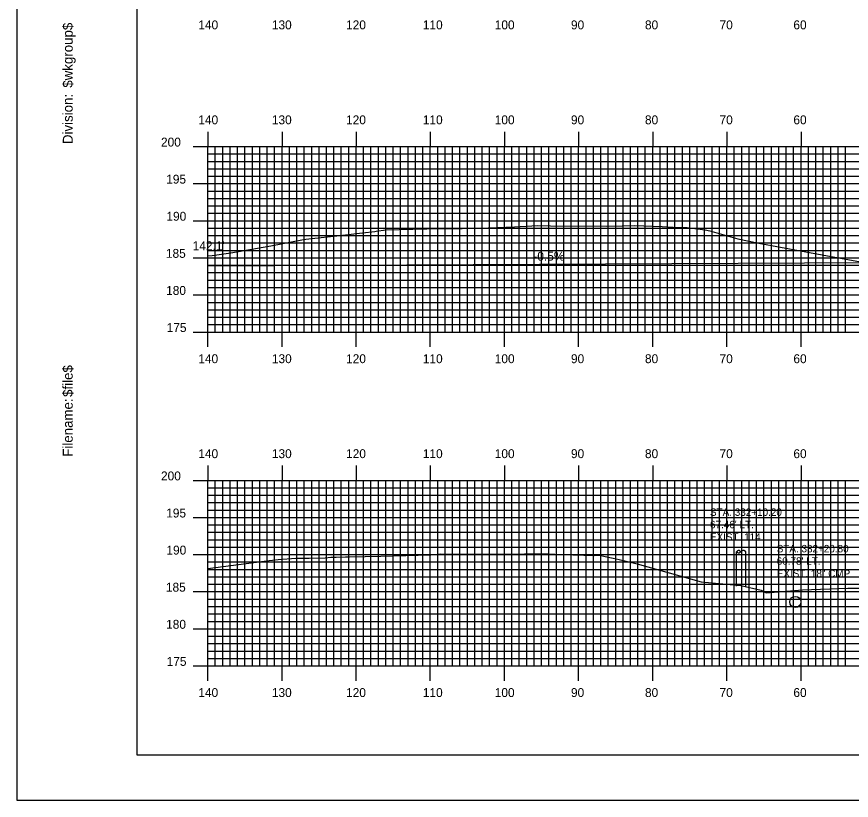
# Model space of a CAD drawing. Extents: x 1822785 to 1823129, y 442591 to 442811.
# Drawn here: x 1822785.5 to 1822898.1, y 442590.5 to 442696.2 of the extents above; entities that cross this region are included whole.
import ezdxf

# ---------------------------------------------------------------- set-up
doc = ezdxf.new("R2010")
doc.units = 0
for name, color, linetype in [('ANNOTATION', 7, 'Continuous'), ('BORDER', 7, 'Continuous'), ('D_Drainage_Culvert', 7, 'Continuous'), ('D_Text_Monospaced', 7, 'Continuous'), ('D_Text_Standard', 7, 'Continuous'), ('H_V ANNOTATION', 7, 'Continuous'), ('MAJOR', 7, 'Continuous'), ('MINOR', 7, 'Continuous'), ('PLOT BOUNDARY', 7, 'Continuous'), ('S_Roadway_Centerline', 7, 'Continuous'), ('S_Utilities_Pole_Power', 7, 'Continuous')]:
    doc.layers.add(name, color=color, linetype=linetype)

msp = doc.modelspace()

# ---------------------------------------------------------------- linework, layer by layer
at = {"layer": 'ANNOTATION'}
for p, q in [((1822811.28, 442662.53), (1822811.28, 442663.94)), ((1822903.76, 442662.99), (1822811.28, 442662.53))]:
    msp.add_line(p, q, dxfattribs=at)
at = {"layer": 'BORDER'}
msp.add_lwpolyline([(1822801.68, 442596.67), (1823121.68, 442596.67), (1823121.68, 442806.67), (1822801.68, 442806.67)], close=True, dxfattribs=at)
at = {"layer": 'D_Drainage_Culvert'}
msp.add_circle((1822890.5, 442617.29), 0.75, dxfattribs=at)
at = {"layer": 'MAJOR'}
for p, q in [((1822811.28, 442680.67), (1822811.28, 442678.67)), ((1822821.28, 442680.67), (1822821.28, 442678.67)), ((1822831.28, 442680.67), (1822831.28, 442678.67)), ((1822841.28, 442680.67), (1822841.28, 442678.67)), ((1822851.28, 442680.67), (1822851.28, 442678.67)), ((1822861.28, 442680.67), (1822861.28, 442678.67)), ((1822871.28, 442680.67), (1822871.28, 442678.67)), ((1822881.28, 442680.67), (1822881.28, 442678.67)), ((1822891.28, 442680.67), (1822891.28, 442678.67)), ((1822809.28, 442678.67), (1822811.28, 442678.67)), ((1822811.28, 442678.67), (1823091.28, 442678.67)), ((1822811.28, 442653.67), (1822811.28, 442678.67)), ((1822811.28, 442653.67), (1822811.28, 442678.67)), ((1822811.28, 442678.67), (1823091.28, 442678.67)), ((1822821.28, 442653.67), (1822821.28, 442678.67)), ((1822831.28, 442653.67), (1822831.28, 442678.67)), ((1822841.28, 442653.67), (1822841.28, 442678.67)), ((1822851.28, 442653.67), (1822851.28, 442678.67)), ((1822861.28, 442653.67), (1822861.28, 442678.67)), ((1822871.28, 442653.67), (1822871.28, 442678.67)), ((1822881.28, 442653.67), (1822881.28, 442678.67)), ((1822891.28, 442653.67), (1822891.28, 442678.67)), ((1822809.28, 442673.67), (1822811.28, 442673.67)), ((1822811.28, 442673.67), (1823091.28, 442673.67)), ((1822809.28, 442668.67), (1822811.28, 442668.67)), ((1822811.28, 442668.67), (1823091.28, 442668.67)), ((1822809.28, 442663.67), (1822811.28, 442663.67)), ((1822811.28, 442663.67), (1823091.28, 442663.67)), ((1822809.28, 442658.67), (1822811.28, 442658.67)), ((1822811.28, 442658.67), (1823091.28, 442658.67)), ((1822809.28, 442653.67), (1822811.28, 442653.67)), ((1822811.28, 442653.67), (1823091.28, 442653.67)), ((1822811.28, 442653.67), (1823091.28, 442653.67)), ((1822811.28, 442651.66), (1822811.28, 442653.67)), ((1822821.28, 442651.66), (1822821.28, 442653.67)), ((1822831.28, 442651.66), (1822831.28, 442653.67)), ((1822841.28, 442651.66), (1822841.28, 442653.67)), ((1822851.28, 442651.66), (1822851.28, 442653.67)), ((1822861.28, 442651.66), (1822861.28, 442653.67)), ((1822871.28, 442651.66), (1822871.28, 442653.67)), ((1822881.28, 442651.66), (1822881.28, 442653.67)), ((1822891.28, 442651.66), (1822891.28, 442653.67)), ((1822811.28, 442635.67), (1822811.28, 442633.67)), ((1822821.28, 442635.67), (1822821.28, 442633.67)), ((1822831.28, 442635.67), (1822831.28, 442633.67)), ((1822841.28, 442635.67), (1822841.28, 442633.67)), ((1822851.28, 442635.67), (1822851.28, 442633.67)), ((1822861.28, 442635.67), (1822861.28, 442633.67)), ((1822871.28, 442635.67), (1822871.28, 442633.67)), ((1822881.28, 442635.67), (1822881.28, 442633.67)), ((1822891.28, 442635.67), (1822891.28, 442633.67)), ((1822809.28, 442633.67), (1822811.28, 442633.67)), ((1822811.28, 442633.67), (1823091.28, 442633.67)), ((1822811.28, 442608.67), (1822811.28, 442633.67)), ((1822811.28, 442608.67), (1822811.28, 442633.67)), ((1822811.28, 442633.67), (1823091.28, 442633.67)), ((1822821.28, 442608.67), (1822821.28, 442633.67)), ((1822831.28, 442608.67), (1822831.28, 442633.67)), ((1822841.28, 442608.67), (1822841.28, 442633.67)), ((1822851.28, 442608.67), (1822851.28, 442633.67)), ((1822861.28, 442608.67), (1822861.28, 442633.67)), ((1822871.28, 442608.67), (1822871.28, 442633.67)), ((1822881.28, 442608.67), (1822881.28, 442633.67)), ((1822891.28, 442608.67), (1822891.28, 442633.67)), ((1822809.28, 442628.67), (1822811.28, 442628.67)), ((1822811.28, 442628.67), (1823091.28, 442628.67)), ((1822809.28, 442623.67), (1822811.28, 442623.67)), ((1822811.28, 442623.67), (1823091.28, 442623.67)), ((1822809.28, 442618.67), (1822811.28, 442618.67)), ((1822811.28, 442618.67), (1823091.28, 442618.67)), ((1822809.28, 442613.67), (1822811.28, 442613.67)), ((1822811.28, 442613.67), (1823091.28, 442613.67)), ((1822809.28, 442608.67), (1822811.28, 442608.67)), ((1822811.28, 442608.67), (1823091.28, 442608.67)), ((1822811.28, 442608.67), (1823091.28, 442608.67)), ((1822811.28, 442606.66), (1822811.28, 442608.67)), ((1822821.28, 442606.66), (1822821.28, 442608.67)), ((1822831.28, 442606.66), (1822831.28, 442608.67)), ((1822841.28, 442606.66), (1822841.28, 442608.67)), ((1822851.28, 442606.66), (1822851.28, 442608.67)), ((1822861.28, 442606.66), (1822861.28, 442608.67)), ((1822871.28, 442606.66), (1822871.28, 442608.67)), ((1822881.28, 442606.66), (1822881.28, 442608.67)), ((1822891.28, 442606.66), (1822891.28, 442608.67))]:
    msp.add_line(p, q, dxfattribs=at)
at = {"layer": 'MINOR'}
for p, q in [((1822812.28, 442653.67), (1822812.28, 442678.67)), ((1822813.28, 442653.67), (1822813.28, 442678.67)), ((1822814.28, 442653.67), (1822814.28, 442678.67)), ((1822815.28, 442653.67), (1822815.28, 442678.67)), ((1822816.28, 442653.67), (1822816.28, 442678.67)), ((1822817.28, 442653.67), (1822817.28, 442678.67)), ((1822818.28, 442653.67), (1822818.28, 442678.67)), ((1822819.28, 442653.67), (1822819.28, 442678.67)), ((1822820.28, 442653.67), (1822820.28, 442678.67)), ((1822822.28, 442653.67), (1822822.28, 442678.67)), ((1822823.28, 442653.67), (1822823.28, 442678.67)), ((1822824.28, 442653.67), (1822824.28, 442678.67)), ((1822825.28, 442653.67), (1822825.28, 442678.67)), ((1822826.28, 442653.67), (1822826.28, 442678.67)), ((1822827.28, 442653.67), (1822827.28, 442678.67)), ((1822828.28, 442653.67), (1822828.28, 442678.67)), ((1822829.28, 442653.67), (1822829.28, 442678.67)), ((1822830.28, 442653.67), (1822830.28, 442678.67)), ((1822832.28, 442653.67), (1822832.28, 442678.67)), ((1822833.28, 442653.67), (1822833.28, 442678.67)), ((1822834.28, 442653.67), (1822834.28, 442678.67)), ((1822835.28, 442653.67), (1822835.28, 442678.67)), ((1822836.28, 442653.67), (1822836.28, 442678.67)), ((1822837.28, 442653.67), (1822837.28, 442678.67)), ((1822838.28, 442653.67), (1822838.28, 442678.67)), ((1822839.28, 442653.67), (1822839.28, 442678.67)), ((1822840.28, 442653.67), (1822840.28, 442678.67)), ((1822842.28, 442653.67), (1822842.28, 442678.67)), ((1822843.28, 442653.67), (1822843.28, 442678.67)), ((1822844.28, 442653.67), (1822844.28, 442678.67)), ((1822845.28, 442653.67), (1822845.28, 442678.67)), ((1822846.28, 442653.67), (1822846.28, 442678.67)), ((1822847.28, 442653.67), (1822847.28, 442678.67)), ((1822848.28, 442653.67), (1822848.28, 442678.67)), ((1822849.28, 442653.67), (1822849.28, 442678.67)), ((1822850.28, 442653.67), (1822850.28, 442678.67)), ((1822852.28, 442653.67), (1822852.28, 442678.67)), ((1822853.28, 442653.67), (1822853.28, 442678.67)), ((1822854.28, 442653.67), (1822854.28, 442678.67)), ((1822855.28, 442653.67), (1822855.28, 442678.67)), ((1822856.28, 442653.67), (1822856.28, 442678.67)), ((1822857.28, 442653.67), (1822857.28, 442678.67)), ((1822858.28, 442653.67), (1822858.28, 442678.67)), ((1822859.28, 442653.67), (1822859.28, 442678.67)), ((1822860.28, 442653.67), (1822860.28, 442678.67)), ((1822862.28, 442653.67), (1822862.28, 442678.67)), ((1822863.28, 442653.67), (1822863.28, 442678.67)), ((1822864.28, 442653.67), (1822864.28, 442678.67)), ((1822865.28, 442653.67), (1822865.28, 442678.67)), ((1822866.28, 442653.67), (1822866.28, 442678.67)), ((1822867.28, 442653.67), (1822867.28, 442678.67)), ((1822868.28, 442653.67), (1822868.28, 442678.67)), ((1822869.28, 442653.67), (1822869.28, 442678.67)), ((1822870.28, 442653.67), (1822870.28, 442678.67)), ((1822872.28, 442653.67), (1822872.28, 442678.67)), ((1822873.28, 442653.67), (1822873.28, 442678.67)), ((1822874.28, 442653.67), (1822874.28, 442678.67)), ((1822875.28, 442653.67), (1822875.28, 442678.67)), ((1822876.28, 442653.67), (1822876.28, 442678.67)), ((1822877.28, 442653.67), (1822877.28, 442678.67)), ((1822878.28, 442653.67), (1822878.28, 442678.67)), ((1822879.28, 442653.67), (1822879.28, 442678.67)), ((1822880.28, 442653.67), (1822880.28, 442678.67)), ((1822882.28, 442653.67), (1822882.28, 442678.67)), ((1822883.28, 442653.67), (1822883.28, 442678.67)), ((1822884.28, 442653.67), (1822884.28, 442678.67)), ((1822885.28, 442653.67), (1822885.28, 442678.67)), ((1822886.28, 442653.67), (1822886.28, 442678.67)), ((1822887.28, 442653.67), (1822887.28, 442678.67)), ((1822888.28, 442653.67), (1822888.28, 442678.67)), ((1822889.28, 442653.67), (1822889.28, 442678.67)), ((1822890.28, 442653.67), (1822890.28, 442678.67)), ((1822892.28, 442653.67), (1822892.28, 442678.67)), ((1822893.28, 442653.67), (1822893.28, 442678.67)), ((1822894.28, 442653.67), (1822894.28, 442678.67)), ((1822895.28, 442653.67), (1822895.28, 442678.67)), ((1822896.28, 442653.67), (1822896.28, 442678.67)), ((1822897.28, 442653.67), (1822897.28, 442678.67)), ((1822811.28, 442677.67), (1823091.28, 442677.67)), ((1822811.28, 442677.67), (1822813.29, 442677.67)), ((1822811.28, 442676.67), (1823091.28, 442676.67)), ((1822811.28, 442676.67), (1822813.29, 442676.67)), ((1822811.28, 442675.67), (1823091.28, 442675.67)), ((1822811.28, 442675.67), (1822813.29, 442675.67)), ((1822811.28, 442674.67), (1823091.28, 442674.67)), ((1822811.28, 442674.67), (1822813.29, 442674.67)), ((1822811.28, 442672.67), (1823091.28, 442672.67)), ((1822811.28, 442672.67), (1822813.29, 442672.67)), ((1822811.28, 442671.67), (1823091.28, 442671.67)), ((1822811.28, 442671.67), (1822813.29, 442671.67)), ((1822811.28, 442670.67), (1823091.28, 442670.67)), ((1822811.28, 442670.67), (1822813.29, 442670.67)), ((1822811.28, 442669.67), (1823091.28, 442669.67)), ((1822811.28, 442669.67), (1822813.29, 442669.67)), ((1822811.28, 442667.67), (1823091.28, 442667.67)), ((1822811.28, 442667.67), (1822813.29, 442667.67)), ((1822811.28, 442666.67), (1823091.28, 442666.67)), ((1822811.28, 442666.67), (1822813.29, 442666.67)), ((1822811.28, 442665.67), (1823091.28, 442665.67)), ((1822811.28, 442665.67), (1822813.29, 442665.67)), ((1822811.28, 442664.67), (1823091.28, 442664.67)), ((1822811.28, 442664.67), (1822813.29, 442664.67)), ((1822811.28, 442662.67), (1823091.28, 442662.67)), ((1822811.28, 442662.67), (1822813.29, 442662.67)), ((1822811.28, 442661.67), (1823091.28, 442661.67)), ((1822811.28, 442661.67), (1822813.29, 442661.67)), ((1822811.28, 442660.67), (1823091.28, 442660.67)), ((1822811.28, 442660.67), (1822813.29, 442660.67)), ((1822811.28, 442659.67), (1823091.28, 442659.67)), ((1822811.28, 442659.67), (1822813.29, 442659.67)), ((1822811.28, 442657.67), (1823091.28, 442657.67)), ((1822811.28, 442657.67), (1822813.29, 442657.67)), ((1822811.28, 442656.67), (1823091.28, 442656.67)), ((1822811.28, 442656.67), (1822813.29, 442656.67)), ((1822811.28, 442655.67), (1823091.28, 442655.67)), ((1822811.28, 442655.67), (1822813.29, 442655.67)), ((1822811.28, 442654.67), (1823091.28, 442654.67)), ((1822811.28, 442654.67), (1822813.29, 442654.67)), ((1822812.28, 442608.67), (1822812.28, 442633.67)), ((1822813.28, 442608.67), (1822813.28, 442633.67)), ((1822814.28, 442608.67), (1822814.28, 442633.67)), ((1822815.28, 442608.67), (1822815.28, 442633.67)), ((1822816.28, 442608.67), (1822816.28, 442633.67)), ((1822817.28, 442608.67), (1822817.28, 442633.67)), ((1822818.28, 442608.67), (1822818.28, 442633.67)), ((1822819.28, 442608.67), (1822819.28, 442633.67)), ((1822820.28, 442608.67), (1822820.28, 442633.67)), ((1822822.28, 442608.67), (1822822.28, 442633.67)), ((1822823.28, 442608.67), (1822823.28, 442633.67)), ((1822824.28, 442608.67), (1822824.28, 442633.67)), ((1822825.28, 442608.67), (1822825.28, 442633.67)), ((1822826.28, 442608.67), (1822826.28, 442633.67)), ((1822827.28, 442608.67), (1822827.28, 442633.67)), ((1822828.28, 442608.67), (1822828.28, 442633.67)), ((1822829.28, 442608.67), (1822829.28, 442633.67)), ((1822830.28, 442608.67), (1822830.28, 442633.67)), ((1822832.28, 442608.67), (1822832.28, 442633.67)), ((1822833.28, 442608.67), (1822833.28, 442633.67)), ((1822834.28, 442608.67), (1822834.28, 442633.67)), ((1822835.28, 442608.67), (1822835.28, 442633.67)), ((1822836.28, 442608.67), (1822836.28, 442633.67)), ((1822837.28, 442608.67), (1822837.28, 442633.67)), ((1822838.28, 442608.67), (1822838.28, 442633.67)), ((1822839.28, 442608.67), (1822839.28, 442633.67)), ((1822840.28, 442608.67), (1822840.28, 442633.67)), ((1822842.28, 442608.67), (1822842.28, 442633.67)), ((1822843.28, 442608.67), (1822843.28, 442633.67)), ((1822844.28, 442608.67), (1822844.28, 442633.67)), ((1822845.28, 442608.67), (1822845.28, 442633.67)), ((1822846.28, 442608.67), (1822846.28, 442633.67)), ((1822847.28, 442608.67), (1822847.28, 442633.67)), ((1822848.28, 442608.67), (1822848.28, 442633.67)), ((1822849.28, 442608.67), (1822849.28, 442633.67)), ((1822850.28, 442608.67), (1822850.28, 442633.67)), ((1822852.28, 442608.67), (1822852.28, 442633.67)), ((1822853.28, 442608.67), (1822853.28, 442633.67)), ((1822854.28, 442608.67), (1822854.28, 442633.67)), ((1822855.28, 442608.67), (1822855.28, 442633.67)), ((1822856.28, 442608.67), (1822856.28, 442633.67)), ((1822857.28, 442608.67), (1822857.28, 442633.67)), ((1822858.28, 442608.67), (1822858.28, 442633.67)), ((1822859.28, 442608.67), (1822859.28, 442633.67)), ((1822860.28, 442608.67), (1822860.28, 442633.67)), ((1822862.28, 442608.67), (1822862.28, 442633.67)), ((1822863.28, 442608.67), (1822863.28, 442633.67)), ((1822864.28, 442608.67), (1822864.28, 442633.67)), ((1822865.28, 442608.67), (1822865.28, 442633.67)), ((1822866.28, 442608.67), (1822866.28, 442633.67)), ((1822867.28, 442608.67), (1822867.28, 442633.67)), ((1822868.28, 442608.67), (1822868.28, 442633.67)), ((1822869.28, 442608.67), (1822869.28, 442633.67)), ((1822870.28, 442608.67), (1822870.28, 442633.67)), ((1822872.28, 442608.67), (1822872.28, 442633.67)), ((1822873.28, 442608.67), (1822873.28, 442633.67)), ((1822874.28, 442608.67), (1822874.28, 442633.67)), ((1822875.28, 442608.67), (1822875.28, 442633.67)), ((1822876.28, 442608.67), (1822876.28, 442633.67)), ((1822877.28, 442608.67), (1822877.28, 442633.67)), ((1822878.28, 442608.67), (1822878.28, 442633.67)), ((1822879.28, 442608.67), (1822879.28, 442633.67)), ((1822880.28, 442608.67), (1822880.28, 442633.67)), ((1822882.28, 442608.67), (1822882.28, 442633.67)), ((1822883.28, 442608.67), (1822883.28, 442633.67)), ((1822884.28, 442608.67), (1822884.28, 442633.67)), ((1822885.28, 442608.67), (1822885.28, 442633.67)), ((1822886.28, 442608.67), (1822886.28, 442633.67)), ((1822887.28, 442608.67), (1822887.28, 442633.67)), ((1822888.28, 442608.67), (1822888.28, 442633.67)), ((1822889.28, 442608.67), (1822889.28, 442633.67)), ((1822890.28, 442608.67), (1822890.28, 442633.67)), ((1822892.28, 442608.67), (1822892.28, 442633.67)), ((1822893.28, 442608.67), (1822893.28, 442633.67)), ((1822894.28, 442608.67), (1822894.28, 442633.67)), ((1822895.28, 442608.67), (1822895.28, 442633.67)), ((1822896.28, 442608.67), (1822896.28, 442633.67)), ((1822897.28, 442608.67), (1822897.28, 442633.67)), ((1822811.28, 442632.67), (1823091.28, 442632.67)), ((1822811.28, 442632.67), (1822813.29, 442632.67)), ((1822811.28, 442631.67), (1823091.28, 442631.67)), ((1822811.28, 442631.67), (1822813.29, 442631.67)), ((1822811.28, 442630.67), (1823091.28, 442630.67)), ((1822811.28, 442630.67), (1822813.29, 442630.67)), ((1822811.28, 442629.67), (1823091.28, 442629.67)), ((1822811.28, 442629.67), (1822813.29, 442629.67)), ((1822811.28, 442627.67), (1823091.28, 442627.67)), ((1822811.28, 442627.67), (1822813.29, 442627.67)), ((1822811.28, 442626.67), (1823091.28, 442626.67)), ((1822811.28, 442626.67), (1822813.29, 442626.67)), ((1822811.28, 442625.67), (1823091.28, 442625.67)), ((1822811.28, 442625.67), (1822813.29, 442625.67)), ((1822811.28, 442624.67), (1823091.28, 442624.67)), ((1822811.28, 442624.67), (1822813.29, 442624.67)), ((1822811.28, 442622.67), (1823091.28, 442622.67)), ((1822811.28, 442622.67), (1822813.29, 442622.67)), ((1822811.28, 442621.67), (1823091.28, 442621.67)), ((1822811.28, 442621.67), (1822813.29, 442621.67)), ((1822811.28, 442620.67), (1823091.28, 442620.67)), ((1822811.28, 442620.67), (1822813.29, 442620.67)), ((1822811.28, 442619.67), (1823091.28, 442619.67)), ((1822811.28, 442619.67), (1822813.29, 442619.67)), ((1822811.28, 442617.67), (1823091.28, 442617.67)), ((1822811.28, 442617.67), (1822813.29, 442617.67)), ((1822811.28, 442616.67), (1823091.28, 442616.67)), ((1822811.28, 442616.67), (1822813.29, 442616.67)), ((1822811.28, 442615.67), (1823091.28, 442615.67)), ((1822811.28, 442615.67), (1822813.29, 442615.67)), ((1822811.28, 442614.67), (1823091.28, 442614.67)), ((1822811.28, 442614.67), (1822813.29, 442614.67)), ((1822811.28, 442612.67), (1823091.28, 442612.67)), ((1822811.28, 442612.67), (1822813.29, 442612.67)), ((1822811.28, 442611.67), (1823091.28, 442611.67)), ((1822811.28, 442611.67), (1822813.29, 442611.67)), ((1822811.28, 442610.67), (1823091.28, 442610.67)), ((1822811.28, 442610.67), (1822813.29, 442610.67)), ((1822811.28, 442609.67), (1823091.28, 442609.67)), ((1822811.28, 442609.67), (1822813.29, 442609.67))]:
    msp.add_line(p, q, dxfattribs=at)
at = {"layer": 'PLOT BOUNDARY'}
msp.add_lwpolyline([(1822785.5, 442590.55), (1823125.5, 442590.55), (1823125.5, 442810.55), (1822785.5, 442810.55)], close=True, dxfattribs=at)
at = {"layer": 'S_Roadway_Centerline'}
for points in [[(1822811.28, 442663.94), (1822811.86, 442663.97), (1822814.38, 442664.34), (1822819.78, 442665.3), (1822824.19, 442666.13), (1822824.48, 442666.18), (1822825.29, 442666.28), (1822828.66, 442666.64), (1822832.12, 442667.04), (1822833.82, 442667.24), (1822833.98, 442667.28), (1822835.28, 442667.44), (1822840.7, 442667.56), (1822840.79, 442667.58), (1822842.57, 442667.62), (1822843.29, 442667.59), (1822847.93, 442667.66), (1822852.65, 442667.84), (1822855.72, 442668.04), (1822857.47, 442667.97), (1822864.99, 442667.93), (1822867.14, 442667.96), (1822868.83, 442668.04), (1822872.55, 442667.88), (1822874.78, 442667.74), (1822874.79, 442667.75), (1822875.94, 442667.77), (1822878.37, 442667.43), (1822878.97, 442667.33), (1822882.75, 442666.24), (1822885.59, 442665.66), (1822891.43, 442664.58), (1822891.46, 442664.58), (1822891.72, 442664.51), (1822891.94, 442664.47), (1822896.35, 442663.67), (1822899.55, 442663.09)], [(1822811.28, 442621.81), (1822819.56, 442622.87), (1822819.98, 442622.93), (1822820.76, 442623.01), (1822823.15, 442623.2), (1822824.92, 442623.19), (1822827.09, 442623.24), (1822827.88, 442623.32), (1822828.6, 442623.34), (1822829.86, 442623.37), (1822830.39, 442623.37), (1822834.6, 442623.45), (1822841.34, 442623.64), (1822842.64, 442623.78), (1822845.44, 442623.74), (1822854, 442623.77), (1822856.17, 442623.8), (1822859.04, 442623.67), (1822863.48, 442623.56), (1822864.08, 442623.57), (1822864.87, 442623.41), (1822865.94, 442623.17), (1822866.73, 442623), (1822869.19, 442622.43), (1822877.82, 442619.99), (1822883.16, 442619.48), (1822885.91, 442618.85), (1822886.57, 442618.52), (1822891.47, 442618.91), (1822897.57, 442619.14), (1822900.15, 442619.12)]]:
    msp.add_lwpolyline(points, dxfattribs=at)
at = {"layer": 'S_Utilities_Pole_Power'}
for p, q in [((1822882.58, 442624.05), (1822882.73, 442624.16)), ((1822882.58, 442619.43), (1822882.58, 442624.05)), ((1822882.73, 442623.94), (1822882.58, 442624.05)), ((1822883.04, 442624.16), (1822883.2, 442624.05)), ((1822883.2, 442624.05), (1822883.04, 442623.94)), ((1822883.36, 442624.16), (1822883.2, 442624.05)), ((1822883.83, 442624.05), (1822883.67, 442624.16)), ((1822883.83, 442619.43), (1822883.83, 442624.05))]:
    msp.add_line(p, q, dxfattribs=at)
for centre, start, end in [((1822882.89, 442623.94), 90, 125.2644), ((1822882.89, 442624.16), 234.7356, 270), ((1822882.89, 442623.94), 54.7356, 90), ((1822882.89, 442624.16), 270, 305.2644), ((1822883.51, 442623.94), 90, 125.2644), ((1822883.51, 442623.94), 54.7356, 90)]:
    msp.add_arc(centre, 0.271, start, end, dxfattribs=at)

# ---------------------------------------------------------------- texts
at = {"layer": 'ANNOTATION'}
msp.add_text('-0.5%', height=1.2, rotation=0.2865, dxfattribs=at).set_placement((1822855.18, 442663.28))
at = {"layer": 'BORDER'}
for s, p in [('$wkgroup$', (1822793.05, 442686.6)), ('Division:', (1822793.05, 442679)), ('$file$', (1822793.05, 442644.92)), ('Filename:', (1822793.05, 442636.86))]:
    msp.add_text(s, height=1.339, rotation=90, dxfattribs=at).set_placement(p)
at = {"layer": 'D_Text_Monospaced'}
for s, p in [('STA. 332+10.20', (1822879, 442628.89)), ("67.46' LT.", (1822879, 442627.22)), ('EXIST. 114', (1822879, 442625.54)), ('STA. 332+20.80', (1822888, 442623.97)), ("60.78' LT.", (1822888, 442622.3)), ('EXIST. 18" CMP', (1822888, 442620.62))]:
    msp.add_text(s, height=1, dxfattribs=at).set_placement(p)
at = {"layer": 'D_Text_Standard'}
msp.add_text("142.1'", height=1.2, dxfattribs=at).set_placement((1822809.23, 442664.7))
at = {"layer": 'H_V ANNOTATION'}
for s, p in [('140', (1822809.99, 442694.47)), ('130', (1822819.91, 442694.47)), ('120', (1822829.92, 442694.47)), ('110', (1822840.27, 442694.47)), ('100', (1822849.97, 442694.47)), ('90', (1822860.25, 442694.47)), ('80', (1822870.23, 442694.47)), ('70', (1822880.29, 442694.47)), ('60', (1822890.25, 442694.47)), ('140', (1822809.99, 442681.67)), ('130', (1822819.91, 442681.67)), ('120', (1822829.92, 442681.67)), ('110', (1822840.27, 442681.67)), ('100', (1822849.97, 442681.67)), ('90', (1822860.25, 442681.67)), ('80', (1822870.23, 442681.67)), ('70', (1822880.29, 442681.67)), ('60', (1822890.25, 442681.67)), ('200', (1822804.96, 442678.67)), ('195', (1822805.66, 442673.67)), ('190', (1822805.69, 442668.67)), ('185', (1822805.62, 442663.67)), ('180', (1822805.65, 442658.67)), ('175', (1822805.72, 442653.67)), ('140', (1822809.99, 442649.47)), ('130', (1822819.91, 442649.47)), ('120', (1822829.92, 442649.47)), ('110', (1822840.27, 442649.47)), ('100', (1822849.97, 442649.47)), ('90', (1822860.25, 442649.47)), ('80', (1822870.23, 442649.47)), ('70', (1822880.29, 442649.47)), ('60', (1822890.25, 442649.47)), ('140', (1822809.99, 442636.67)), ('130', (1822819.91, 442636.67)), ('120', (1822829.92, 442636.67)), ('110', (1822840.27, 442636.67)), ('100', (1822849.97, 442636.67)), ('90', (1822860.25, 442636.67)), ('80', (1822870.23, 442636.67)), ('70', (1822880.29, 442636.67)), ('60', (1822890.25, 442636.67)), ('200', (1822804.96, 442633.67)), ('195', (1822805.66, 442628.67)), ('190', (1822805.69, 442623.67)), ('185', (1822805.62, 442618.67)), ('180', (1822805.65, 442613.67)), ('175', (1822805.72, 442608.67)), ('140', (1822809.99, 442604.47)), ('130', (1822819.91, 442604.47)), ('120', (1822829.92, 442604.47)), ('110', (1822840.27, 442604.47)), ('100', (1822849.97, 442604.47)), ('90', (1822860.25, 442604.47)), ('80', (1822870.23, 442604.47)), ('70', (1822880.29, 442604.47)), ('60', (1822890.25, 442604.47))]:
    msp.add_text(s, height=1.2, dxfattribs=at).set_placement(p)
at = {"layer": 'MAJOR'}
for p in [(1822811.27, 442653.67), (1822811.27, 442608.67)]:
    msp.add_text('-', height=0.012, dxfattribs=at).set_placement(p)
at = {"layer": 'S_Roadway_Centerline'}
for s, p in [('C', (1822855.72, 442668.04)), ('L', (1822855.72, 442668.03)), ('C', (1822842.63, 442623.78)), ('L', (1822842.63, 442623.78))]:
    msp.add_text(s, height=0.0146, dxfattribs=at).set_placement(p)

doc.saveas('drawing.dxf')
